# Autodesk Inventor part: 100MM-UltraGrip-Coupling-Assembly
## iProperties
Created: 2012-06
Part Number: 100MM-UltraGrip-Coupling-Assembly
Document SubType Name: Modeling
Designer: D Cole
Density: 1 g/cm^3
Author: D Cole
